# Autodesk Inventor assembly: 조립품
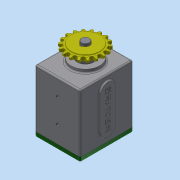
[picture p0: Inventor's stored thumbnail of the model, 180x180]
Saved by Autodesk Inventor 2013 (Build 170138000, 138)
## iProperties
Created: 2018-12
Part Number: 조립품
Document SubType Name: Assembly
Designer: dgall
Mass: 2998.66 g
Surface Area: 1968.3 cm^2
Volume: 816.157 cm^3
Density: 3.67413 g/cm^3
Author: dgall
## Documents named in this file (16)
- C:\Users\dgall\Desktop\381207V1056\조립품.iam
- C:\Users\dgall\Desktop\381207V1056\본체.ipt
- C:\Users\dgall\Desktop\381207V1056\가변스프링.ipt
- C:\Users\dgall\Desktop\381207V1056\멈춤나사 M3x8.ipt
- C:\Users\dgall\Desktop\381207V1056\메인 기어 축.ipt
- C:\Users\dgall\Desktop\381207V1056\베어링 6003.ipt
- C:\Users\dgall\Desktop\381207V1056\부시.ipt
- C:\Users\dgall\Desktop\381207V1056\서브 기어 축.ipt
- C:\Users\dgall\Desktop\381207V1056\스프로킷.ipt
- C:\Users\dgall\Desktop\381207V1056\슬라이더.ipt
- C:\Users\dgall\Desktop\381207V1056\커버.ipt
- C:\Users\dgall\Desktop\381207V1056\키 5 x 5 x 18.ipt
- C:\Users\dgall\Desktop\381207V1056\베어링 608.ipt
- C:\Users\dgall\Desktop\381207V1056\오일 실 8 22 7.ipt
- C:\Users\dgall\Desktop\381207V1056\오일 실 17 32 8.ipt
- C:\Users\dgall\Desktop\381207V1056\볼트 M4 x 10.ipt
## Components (1 placed, 1 different names)
1. 가변스프링:1
